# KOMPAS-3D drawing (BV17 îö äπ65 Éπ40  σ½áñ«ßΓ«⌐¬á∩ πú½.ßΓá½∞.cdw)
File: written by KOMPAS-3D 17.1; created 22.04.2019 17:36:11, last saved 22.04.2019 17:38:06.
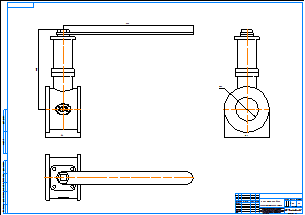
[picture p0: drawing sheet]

Sheet 1: A1, landscape

Title block, sheet 1: name: BV17 МФ Ду65 Ру40 / хладостойкая угл.сталь; material: Внимание! Данный продукт является объектом авторского права ООО «Торговый Дом АДЛ». / Запрещается изменение, копирование, распространение / (в том числе путем копирования на другие сайты и ресурсы в Интернете) / или любое иное использование информации и объектов без предварительного / согласия правообладателя (ООО «Торговый Дом АДЛ»).; mass: 9,23; sheets: 1; organisation: ООО "Торговый дом АДЛ"; sheet format: A1; stored path: \\adlc.lan\data\АДЛ_ПКД\3D-модели\ADL production\Краны шаровые серии BV\BV17 МФ хладостойкая угл.сталь Ру40\KOMPAS 2D\BV17 МФ Ду65 Ру40  хладостойкая угл.сталь.cdw

Views: Вид 1, Проекционный вид 2, Проекционный вид 3
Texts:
  user
Dimensions and other numbers on the sheet: 360; 221; 98; 127; 65; 1:1; 1; 9,23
